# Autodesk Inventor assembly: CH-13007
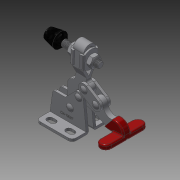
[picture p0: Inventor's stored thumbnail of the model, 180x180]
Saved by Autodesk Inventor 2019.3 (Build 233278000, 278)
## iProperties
Company: Î¢ÈíÖÐ¹ú
Created: 2012-09
Part Number: CH-13007
Material: Ogólny
Description: STEP AP203
Document SubType Name: Assembly
Designer: CADENGINEERING4
Stock Number: DOCISK PIONOWY
Sending System: SolidWorks 2010
Preprocessor: SwSTEP 2.0
Title: CH-13007.STEP
Author: Î¢ÈíÓÃ»§
Revision Number: ÈÎºÎ
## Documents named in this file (9)
- D:\Vault_2016\Projekty\Clamptek\STRONA\Vertical toggle clamp\CH-13007\CH-13007_OTWARTY.iam
- D:\Vault_2016\Projekty\Clamptek\STRONA\Vertical toggle clamp\CH-13007\CH-FC-56212 Nut.ipt
- D:\Vault_2016\Projekty\Clamptek\STRONA\Vertical toggle clamp\CH-13007\CH-13007-04 CONNECTING-PLATE.ipt
- D:\Vault_2016\Projekty\Clamptek\STRONA\Vertical toggle clamp\CH-13007\CH-13007-01 FLANGED BASE.ipt
- D:\Vault_2016\Projekty\Clamptek\STRONA\Vertical toggle clamp\CH-13007\CH-13007-05 .ipt
- D:\Vault_2016\Projekty\Clamptek\STRONA\Vertical toggle clamp\CH-13007\CH-FW-516.ipt
- D:\Vault_2016\Projekty\Clamptek\STRONA\Vertical toggle clamp\CH-13007\CH-FC-56212 SPINDLE SUPPLIED.ipt
- D:\Vault_2016\Projekty\Clamptek\STRONA\Vertical toggle clamp\CH-13007\CH-13007-02 U-BAR.ipt
- D:\Vault_2016\Projekty\Clamptek\STRONA\Vertical toggle clamp\CH-13007\CH-13007-03 T-HANDLE.ipt
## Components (14 placed, 14 different names)
1. CH-FC-56212 Nut_1 — Zestawiające:24, Zestawiające:25
2. CH-13007-04 CONNECTING-PLATE_2 — Zestawiające:5, Zestawiające:6, Zestawiające:10
3. CH-13007-01 FLANGED BASE_3 — Zestawiające:1, Zestawiające:2, Zestawiające:7, Zestawiające:8, Zestawiające:13, Zestawiające:14, Zestawiające:15, Zestawiające:16
4. CH-13007-05 _4 — Zestawiające:11, Zestawiające:18
5. CH-FW-516_5 — Zestawiające:20, Zestawiające:22, Zestawiające:23, Kątowe:1, Zestawiające:24, Zestawiające:25
6. CH-FW-516_6 — Zestawiające:21, Zestawiające:22, Kątowe:2, Zestawiające:26, Zestawiające:27, Równoległe:1
7. CH-13007-05 _7 — Zestawiające:12, Zestawiające:17
8. CH-13007-05 _8 — Zestawiające:14, Zestawiające:15
9. CH-13007-04 CONNECTING-PLATE_9 — Zestawiające:3, Zestawiające:4, Zestawiające:9, Zestawiające:11, Zestawiające:12, Zestawiające:17, Zestawiające:18
10. CH-FC-56212 SPINDLE SUPPLIED_10 — Zestawiające:28, Równoległe:1, Zestawiające:30
11. CH-13007-02 U-BAR_11 — Zestawiające:2, Zestawiające:4, Zestawiające:5, Zestawiające:8, Zestawiające:20, Zestawiające:21, Zestawiające:23, Kątowe:1, Kątowe:2, Zestawiające:29, Zestawiające:30
12. CH-13007-05 _12 — Zestawiające:13, Zestawiające:16
13. CH-13007-03 T-HANDLE_13 — Zestawiające:1, Zestawiające:3, Zestawiające:6, Zestawiające:7, Zestawiające:9, Zestawiające:10, Zestawiające:29
14. CH-FC-56212 Nut_14 — Zestawiające:26, Zestawiające:27, Zestawiające:28
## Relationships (32: Mate 29, Angle 2, Flush 1)
- Zestawiające:1 [Mate]: CH-13007-01 FLANGED BASE_3 ↔ CH-13007-03 T-HANDLE_13
- Zestawiające:2 [Mate]: CH-13007-01 FLANGED BASE_3 ↔ CH-13007-02 U-BAR_11
- Zestawiające:3 [Mate]: CH-13007-04 CONNECTING-PLATE_9 ↔ CH-13007-03 T-HANDLE_13
- Zestawiające:4 [Mate]: CH-13007-04 CONNECTING-PLATE_9 ↔ CH-13007-02 U-BAR_11
- Zestawiające:5 [Mate]: CH-13007-04 CONNECTING-PLATE_2 ↔ CH-13007-02 U-BAR_11
- Zestawiające:6 [Mate]: CH-13007-04 CONNECTING-PLATE_2 ↔ CH-13007-03 T-HANDLE_13
- Zestawiające:7 [Mate]: CH-13007-01 FLANGED BASE_3 ↔ CH-13007-03 T-HANDLE_13
- Zestawiające:8 [Mate]: CH-13007-01 FLANGED BASE_3 ↔ CH-13007-02 U-BAR_11
- Zestawiające:9 [Mate]: CH-13007-04 CONNECTING-PLATE_9 ↔ CH-13007-03 T-HANDLE_13
- Zestawiające:10 [Mate]: CH-13007-04 CONNECTING-PLATE_2 ↔ CH-13007-03 T-HANDLE_13
- Zestawiające:11 [Mate]: CH-13007-05 _4 ↔ CH-13007-04 CONNECTING-PLATE_9
- Zestawiające:12 [Mate]: CH-13007-05 _7 ↔ CH-13007-04 CONNECTING-PLATE_9
- Zestawiające:13 [Mate]: CH-13007-01 FLANGED BASE_3 ↔ CH-13007-05 _12
- Zestawiające:14 [Mate]: CH-13007-01 FLANGED BASE_3 ↔ CH-13007-05 _8
- Zestawiające:15 [Mate]: CH-13007-01 FLANGED BASE_3 ↔ CH-13007-05 _8
- Zestawiające:16 [Mate]: CH-13007-01 FLANGED BASE_3 ↔ CH-13007-05 _12
- Zestawiające:17 [Mate]: CH-13007-05 _7 ↔ CH-13007-04 CONNECTING-PLATE_9
- Zestawiające:18 [Mate]: CH-13007-05 _4 ↔ CH-13007-04 CONNECTING-PLATE_9
- Zestawiające:20 [Mate]: CH-FW-516_5 ↔ CH-13007-02 U-BAR_11
- Zestawiające:21 [Mate]: CH-FW-516_6 ↔ CH-13007-02 U-BAR_11
- Zestawiające:22 [Mate]: CH-FW-516_5 ↔ CH-FW-516_6
- Zestawiające:23 [Mate]: CH-FW-516_5 ↔ CH-13007-02 U-BAR_11
- Kątowe:1 [Angle]: CH-FW-516_5 ↔ CH-13007-02 U-BAR_11
- Kątowe:2 [Angle]: CH-FW-516_6 ↔ CH-13007-02 U-BAR_11
- Zestawiające:24 [Mate]: CH-FC-56212 Nut_1 ↔ CH-FW-516_5
- Zestawiające:25 [Mate]: CH-FC-56212 Nut_1 ↔ CH-FW-516_5
- Zestawiające:26 [Mate]: CH-FW-516_6 ↔ CH-FC-56212 Nut_14
- Zestawiające:27 [Mate]: CH-FW-516_6 ↔ CH-FC-56212 Nut_14
- Zestawiające:28 [Mate]: CH-FC-56212 SPINDLE SUPPLIED_10 ↔ CH-FC-56212 Nut_14
- Równoległe:1 [Flush]: CH-FW-516_6 ↔ CH-FC-56212 SPINDLE SUPPLIED_10
- Zestawiające:29 [Mate]: CH-13007-02 U-BAR_11 ↔ CH-13007-03 T-HANDLE_13
- Zestawiające:30 [Mate]: CH-FC-56212 SPINDLE SUPPLIED_10 ↔ CH-13007-02 U-BAR_11
